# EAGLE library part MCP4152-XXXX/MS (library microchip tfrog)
MCP4152 7/8-Bit Single SPI Digital Rheostat with Volatile Memory Doc: http://www.microchip.com/wwwproducts/Devices.aspx?dDocName=en531890 Ref Used: MCP4152-502E/MS (8 bits, 5K ohms)
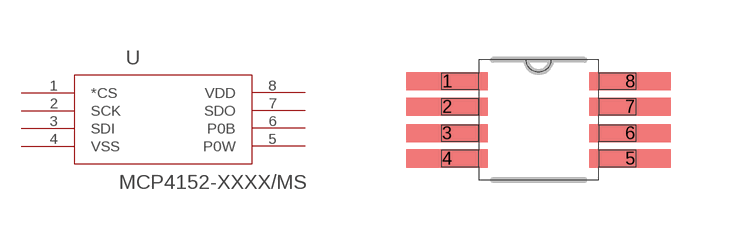
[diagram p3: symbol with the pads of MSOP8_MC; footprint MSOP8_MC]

Designator prefix -

## MCP4152-XXXX/MS  [MSOP8_MC]
1  *CS  pas
2  SCK  pas
3  SDI  pas
4  VSS  pas
5  P0W  pas
6  P0B  pas
7  SDO  pas
8  VDD  pas

## Footprint MSOP8_MC (pad centres in mm)
MSOP8 with long pads (0.08inch instead of 0.06)
smd 2.032 x 0.457: 1 -2.286,0.965; 2 -2.286,0.33; 3 -2.286,-0.33; 4 -2.286,-0.965; 5 2.286,-0.965; 6 2.286,-0.33; 7 2.286,0.33; 8 2.286,0.965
